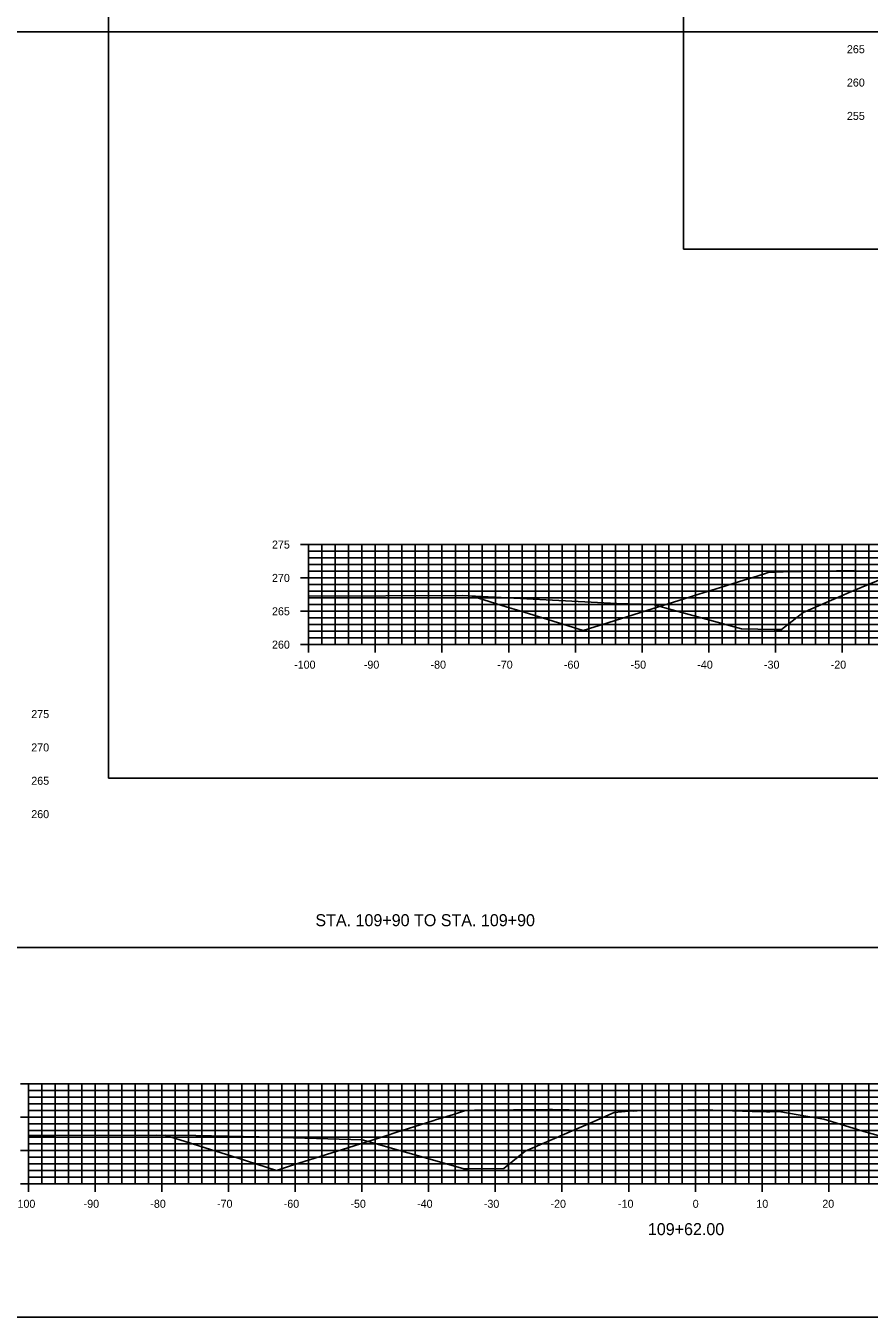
# Model space of a CAD drawing. Extents: x 1661012 to 1662122, y 670053 to 671852.
# Drawn here: x 1661264.3 to 1661390.7, y 671488.8 to 671682.4 of the extents above; entities that cross this region are included whole.
import ezdxf

# ---------------------------------------------------------------- set-up
doc = ezdxf.new("R2010")
doc.units = 0
for name, color, linetype in [('R_Concrete', 7, 'Continuous'), ('R_Concrete Hidden', 7, 'Continuous'), ('R_Erosion', 7, 'Continuous'), ('R_Exist Surface', 7, 'Continuous'), ('R_Proposed Road', 7, 'Continuous'), ('R_ROW Annot', 7, 'Continuous')]:
    doc.layers.add(name, color=color, linetype=linetype)

msp = doc.modelspace()

# ---------------------------------------------------------------- linework, layer by layer
at = {"layer": 'R_Concrete'}
for p, q in [((1661305.45, 671604.66), (1661307.85, 671604.66)), ((1661306.65, 671604.66), (1661506.65, 671604.66)), ((1661306.65, 671589.66), (1661306.65, 671604.66)), ((1661306.65, 671603.66), (1661506.65, 671603.66)), ((1661306.65, 671603.66), (1661307.25, 671603.66)), ((1661308.65, 671589.66), (1661308.65, 671604.66)), ((1661310.65, 671589.66), (1661310.65, 671604.66)), ((1661312.65, 671589.66), (1661312.65, 671604.66)), ((1661314.65, 671589.66), (1661314.65, 671604.66)), ((1661316.65, 671589.66), (1661316.65, 671604.66)), ((1661318.65, 671589.66), (1661318.65, 671604.66)), ((1661320.65, 671589.66), (1661320.65, 671604.66)), ((1661322.65, 671589.66), (1661322.65, 671604.66)), ((1661324.65, 671589.66), (1661324.65, 671604.66)), ((1661326.65, 671589.66), (1661326.65, 671604.66)), ((1661328.65, 671589.66), (1661328.65, 671604.66)), ((1661330.65, 671589.66), (1661330.65, 671604.66)), ((1661332.65, 671589.66), (1661332.65, 671604.66)), ((1661334.65, 671589.66), (1661334.65, 671604.66)), ((1661336.65, 671589.66), (1661336.65, 671604.66)), ((1661338.65, 671589.66), (1661338.65, 671604.66)), ((1661340.65, 671589.66), (1661340.65, 671604.66)), ((1661342.65, 671589.66), (1661342.65, 671604.66)), ((1661344.65, 671589.66), (1661344.65, 671604.66)), ((1661346.65, 671589.66), (1661346.65, 671604.66)), ((1661348.65, 671589.66), (1661348.65, 671604.66)), ((1661350.65, 671589.66), (1661350.65, 671604.66)), ((1661352.65, 671589.66), (1661352.65, 671604.66)), ((1661354.65, 671589.66), (1661354.65, 671604.66)), ((1661356.65, 671589.66), (1661356.65, 671604.66)), ((1661358.65, 671589.66), (1661358.65, 671604.66)), ((1661360.65, 671589.66), (1661360.65, 671604.66)), ((1661362.65, 671589.66), (1661362.65, 671604.66)), ((1661364.65, 671589.66), (1661364.65, 671604.66)), ((1661366.65, 671589.66), (1661366.65, 671604.66)), ((1661368.65, 671589.66), (1661368.65, 671604.66)), ((1661370.65, 671589.66), (1661370.65, 671604.66)), ((1661372.65, 671589.66), (1661372.65, 671604.66)), ((1661374.65, 671589.66), (1661374.65, 671604.66)), ((1661376.65, 671589.66), (1661376.65, 671604.66)), ((1661378.65, 671589.66), (1661378.65, 671604.66)), ((1661380.65, 671589.66), (1661380.65, 671604.66)), ((1661382.65, 671589.66), (1661382.65, 671604.66)), ((1661384.65, 671589.66), (1661384.65, 671604.66)), ((1661386.65, 671589.66), (1661386.65, 671604.66)), ((1661388.65, 671589.66), (1661388.65, 671604.66)), ((1661390.65, 671589.66), (1661390.65, 671604.66)), ((1661306.65, 671602.66), (1661506.65, 671602.66)), ((1661306.65, 671602.66), (1661307.25, 671602.66)), ((1661306.65, 671601.66), (1661506.65, 671601.66)), ((1661306.65, 671601.66), (1661307.25, 671601.66)), ((1661305.45, 671599.66), (1661307.85, 671599.66)), ((1661306.65, 671600.66), (1661506.65, 671600.66)), ((1661306.65, 671600.66), (1661307.25, 671600.66)), ((1661306.65, 671599.66), (1661506.65, 671599.66)), ((1661306.65, 671598.66), (1661506.65, 671598.66)), ((1661306.65, 671598.66), (1661307.25, 671598.66)), ((1661306.65, 671597.66), (1661506.65, 671597.66)), ((1661306.65, 671597.66), (1661307.25, 671597.66)), ((1661306.65, 671596.66), (1661506.65, 671596.66)), ((1661306.65, 671596.66), (1661307.25, 671596.66)), ((1661306.65, 671595.66), (1661506.65, 671595.66)), ((1661306.65, 671595.66), (1661307.25, 671595.66)), ((1661305.45, 671594.66), (1661307.85, 671594.66)), ((1661306.65, 671594.66), (1661506.65, 671594.66)), ((1661306.65, 671593.66), (1661506.65, 671593.66)), ((1661306.65, 671593.66), (1661307.25, 671593.66)), ((1661306.65, 671592.66), (1661506.65, 671592.66)), ((1661306.65, 671592.66), (1661307.25, 671592.66)), ((1661306.65, 671591.66), (1661506.65, 671591.66)), ((1661306.65, 671591.66), (1661307.25, 671591.66)), ((1661305.45, 671589.66), (1661307.85, 671589.66)), ((1661306.65, 671588.46), (1661306.65, 671590.86)), ((1661306.65, 671590.66), (1661506.65, 671590.66)), ((1661306.65, 671590.66), (1661307.25, 671590.66)), ((1661306.65, 671589.66), (1661506.65, 671589.66)), ((1661308.65, 671589.66), (1661308.65, 671590.26)), ((1661310.65, 671589.66), (1661310.65, 671590.26)), ((1661312.65, 671589.66), (1661312.65, 671590.26)), ((1661314.65, 671589.66), (1661314.65, 671590.26)), ((1661316.65, 671588.46), (1661316.65, 671590.86)), ((1661318.65, 671589.66), (1661318.65, 671590.26)), ((1661320.65, 671589.66), (1661320.65, 671590.26)), ((1661322.65, 671589.66), (1661322.65, 671590.26)), ((1661324.65, 671589.66), (1661324.65, 671590.26)), ((1661326.65, 671588.46), (1661326.65, 671590.86)), ((1661328.65, 671589.66), (1661328.65, 671590.26)), ((1661330.65, 671589.66), (1661330.65, 671590.26)), ((1661332.65, 671589.66), (1661332.65, 671590.26)), ((1661334.65, 671589.66), (1661334.65, 671590.26)), ((1661336.65, 671588.46), (1661336.65, 671590.86)), ((1661338.65, 671589.66), (1661338.65, 671590.26)), ((1661340.65, 671589.66), (1661340.65, 671590.26)), ((1661342.65, 671589.66), (1661342.65, 671590.26)), ((1661344.65, 671589.66), (1661344.65, 671590.26)), ((1661346.65, 671588.46), (1661346.65, 671590.86)), ((1661348.65, 671589.66), (1661348.65, 671590.26)), ((1661350.65, 671589.66), (1661350.65, 671590.26)), ((1661352.65, 671589.66), (1661352.65, 671590.26)), ((1661354.65, 671589.66), (1661354.65, 671590.26)), ((1661356.65, 671588.46), (1661356.65, 671590.86)), ((1661358.65, 671589.66), (1661358.65, 671590.26)), ((1661360.65, 671589.66), (1661360.65, 671590.26)), ((1661362.65, 671589.66), (1661362.65, 671590.26)), ((1661364.65, 671589.66), (1661364.65, 671590.26)), ((1661366.65, 671588.46), (1661366.65, 671590.86)), ((1661368.65, 671589.66), (1661368.65, 671590.26)), ((1661370.65, 671589.66), (1661370.65, 671590.26)), ((1661372.65, 671589.66), (1661372.65, 671590.26)), ((1661374.65, 671589.66), (1661374.65, 671590.26)), ((1661376.65, 671588.46), (1661376.65, 671590.86)), ((1661378.65, 671589.66), (1661378.65, 671590.26)), ((1661380.65, 671589.66), (1661380.65, 671590.26)), ((1661382.65, 671589.66), (1661382.65, 671590.26)), ((1661384.65, 671589.66), (1661384.65, 671590.26)), ((1661386.65, 671588.46), (1661386.65, 671590.86)), ((1661388.65, 671589.66), (1661388.65, 671590.26)), ((1661390.65, 671589.66), (1661390.65, 671590.26)), ((1661263.44, 671523.84), (1661265.84, 671523.84)), ((1661264.64, 671523.84), (1661464.64, 671523.84)), ((1661264.64, 671508.84), (1661264.64, 671523.84)), ((1661266.64, 671508.84), (1661266.64, 671523.84)), ((1661268.64, 671508.84), (1661268.64, 671523.84)), ((1661270.64, 671508.84), (1661270.64, 671523.84)), ((1661272.64, 671508.84), (1661272.64, 671523.84)), ((1661274.64, 671508.84), (1661274.64, 671523.84)), ((1661276.64, 671508.84), (1661276.64, 671523.84)), ((1661278.64, 671508.84), (1661278.64, 671523.84)), ((1661280.64, 671508.84), (1661280.64, 671523.84)), ((1661282.64, 671508.84), (1661282.64, 671523.84)), ((1661284.64, 671508.84), (1661284.64, 671523.84)), ((1661286.64, 671508.84), (1661286.64, 671523.84)), ((1661288.64, 671508.84), (1661288.64, 671523.84)), ((1661290.64, 671508.84), (1661290.64, 671523.84)), ((1661292.64, 671508.84), (1661292.64, 671523.84)), ((1661294.64, 671508.84), (1661294.64, 671523.84)), ((1661296.64, 671508.84), (1661296.64, 671523.84)), ((1661298.64, 671508.84), (1661298.64, 671523.84)), ((1661300.64, 671508.84), (1661300.64, 671523.84)), ((1661302.64, 671508.84), (1661302.64, 671523.84)), ((1661304.64, 671508.84), (1661304.64, 671523.84)), ((1661306.64, 671508.84), (1661306.64, 671523.84)), ((1661308.64, 671508.84), (1661308.64, 671523.84)), ((1661310.64, 671508.84), (1661310.64, 671523.84)), ((1661312.64, 671508.84), (1661312.64, 671523.84)), ((1661314.64, 671508.84), (1661314.64, 671523.84)), ((1661316.64, 671508.84), (1661316.64, 671523.84)), ((1661318.64, 671508.84), (1661318.64, 671523.84)), ((1661320.64, 671508.84), (1661320.64, 671523.84)), ((1661322.64, 671508.84), (1661322.64, 671523.84)), ((1661324.64, 671508.84), (1661324.64, 671523.84)), ((1661326.64, 671508.84), (1661326.64, 671523.84)), ((1661328.64, 671508.84), (1661328.64, 671523.84)), ((1661330.64, 671508.84), (1661330.64, 671523.84)), ((1661332.64, 671508.84), (1661332.64, 671523.84)), ((1661334.64, 671508.84), (1661334.64, 671523.84)), ((1661336.64, 671508.84), (1661336.64, 671523.84)), ((1661338.64, 671508.84), (1661338.64, 671523.84)), ((1661340.64, 671508.84), (1661340.64, 671523.84)), ((1661342.64, 671508.84), (1661342.64, 671523.84)), ((1661344.64, 671508.84), (1661344.64, 671523.84)), ((1661346.64, 671508.84), (1661346.64, 671523.84)), ((1661348.64, 671508.84), (1661348.64, 671523.84)), ((1661350.64, 671508.84), (1661350.64, 671523.84)), ((1661352.64, 671508.84), (1661352.64, 671523.84)), ((1661354.64, 671508.84), (1661354.64, 671523.84)), ((1661356.64, 671508.84), (1661356.64, 671523.84)), ((1661358.64, 671508.84), (1661358.64, 671523.84)), ((1661360.64, 671508.84), (1661360.64, 671523.84)), ((1661362.64, 671508.84), (1661362.64, 671523.84)), ((1661364.64, 671508.84), (1661364.64, 671523.84)), ((1661366.64, 671508.84), (1661366.64, 671523.84)), ((1661368.64, 671508.84), (1661368.64, 671523.84)), ((1661370.64, 671508.84), (1661370.64, 671523.84)), ((1661372.64, 671508.84), (1661372.64, 671523.84)), ((1661374.64, 671508.84), (1661374.64, 671523.84)), ((1661376.64, 671508.84), (1661376.64, 671523.84)), ((1661378.64, 671508.84), (1661378.64, 671523.84)), ((1661380.64, 671508.84), (1661380.64, 671523.84)), ((1661382.64, 671508.84), (1661382.64, 671523.84)), ((1661384.64, 671508.84), (1661384.64, 671523.84)), ((1661386.64, 671508.84), (1661386.64, 671523.84)), ((1661388.64, 671508.84), (1661388.64, 671523.84)), ((1661390.64, 671508.84), (1661390.64, 671523.84)), ((1661264.64, 671522.84), (1661464.64, 671522.84)), ((1661264.64, 671522.84), (1661265.24, 671522.84)), ((1661264.64, 671521.84), (1661464.64, 671521.84)), ((1661264.64, 671521.84), (1661265.24, 671521.84)), ((1661264.64, 671520.84), (1661464.64, 671520.84)), ((1661264.64, 671520.84), (1661265.24, 671520.84)), ((1661264.64, 671519.84), (1661464.64, 671519.84)), ((1661264.64, 671519.84), (1661265.24, 671519.84)), ((1661263.44, 671518.84), (1661265.84, 671518.84)), ((1661264.64, 671518.84), (1661464.64, 671518.84)), ((1661264.64, 671517.84), (1661464.64, 671517.84)), ((1661264.64, 671517.84), (1661265.24, 671517.84)), ((1661264.64, 671516.84), (1661464.64, 671516.84)), ((1661264.64, 671516.84), (1661265.24, 671516.84)), ((1661264.64, 671515.84), (1661464.64, 671515.84)), ((1661264.64, 671515.84), (1661265.24, 671515.84)), ((1661264.64, 671514.84), (1661464.64, 671514.84)), ((1661264.64, 671514.84), (1661265.24, 671514.84)), ((1661263.44, 671513.84), (1661265.84, 671513.84)), ((1661264.64, 671513.84), (1661464.64, 671513.84)), ((1661264.64, 671512.84), (1661464.64, 671512.84)), ((1661264.64, 671512.84), (1661265.24, 671512.84)), ((1661264.64, 671511.84), (1661464.64, 671511.84)), ((1661264.64, 671511.84), (1661265.24, 671511.84)), ((1661264.64, 671510.84), (1661464.64, 671510.84)), ((1661264.64, 671510.84), (1661265.24, 671510.84)), ((1661263.44, 671508.84), (1661265.84, 671508.84)), ((1661264.64, 671507.64), (1661264.64, 671510.04)), ((1661264.64, 671509.84), (1661464.64, 671509.84)), ((1661264.64, 671509.84), (1661265.24, 671509.84)), ((1661264.64, 671508.84), (1661464.64, 671508.84)), ((1661266.64, 671508.84), (1661266.64, 671509.44)), ((1661268.64, 671508.84), (1661268.64, 671509.44)), ((1661270.64, 671508.84), (1661270.64, 671509.44)), ((1661272.64, 671508.84), (1661272.64, 671509.44)), ((1661274.64, 671507.64), (1661274.64, 671510.04)), ((1661276.64, 671508.84), (1661276.64, 671509.44)), ((1661278.64, 671508.84), (1661278.64, 671509.44)), ((1661280.64, 671508.84), (1661280.64, 671509.44)), ((1661282.64, 671508.84), (1661282.64, 671509.44)), ((1661284.64, 671507.64), (1661284.64, 671510.04)), ((1661286.64, 671508.84), (1661286.64, 671509.44)), ((1661288.64, 671508.84), (1661288.64, 671509.44)), ((1661290.64, 671508.84), (1661290.64, 671509.44)), ((1661292.64, 671508.84), (1661292.64, 671509.44)), ((1661294.64, 671507.64), (1661294.64, 671510.04)), ((1661296.64, 671508.84), (1661296.64, 671509.44)), ((1661298.64, 671508.84), (1661298.64, 671509.44)), ((1661300.64, 671508.84), (1661300.64, 671509.44)), ((1661302.64, 671508.84), (1661302.64, 671509.44)), ((1661304.64, 671507.64), (1661304.64, 671510.04)), ((1661306.64, 671508.84), (1661306.64, 671509.44)), ((1661308.64, 671508.84), (1661308.64, 671509.44)), ((1661310.64, 671508.84), (1661310.64, 671509.44)), ((1661312.64, 671508.84), (1661312.64, 671509.44)), ((1661314.64, 671507.64), (1661314.64, 671510.04)), ((1661316.64, 671508.84), (1661316.64, 671509.44)), ((1661318.64, 671508.84), (1661318.64, 671509.44)), ((1661320.64, 671508.84), (1661320.64, 671509.44)), ((1661322.64, 671508.84), (1661322.64, 671509.44)), ((1661324.64, 671507.64), (1661324.64, 671510.04)), ((1661326.64, 671508.84), (1661326.64, 671509.44)), ((1661328.64, 671508.84), (1661328.64, 671509.44)), ((1661330.64, 671508.84), (1661330.64, 671509.44)), ((1661332.64, 671508.84), (1661332.64, 671509.44)), ((1661334.64, 671507.64), (1661334.64, 671510.04)), ((1661336.64, 671508.84), (1661336.64, 671509.44)), ((1661338.64, 671508.84), (1661338.64, 671509.44)), ((1661340.64, 671508.84), (1661340.64, 671509.44)), ((1661342.64, 671508.84), (1661342.64, 671509.44)), ((1661344.64, 671507.64), (1661344.64, 671510.04)), ((1661346.64, 671508.84), (1661346.64, 671509.44)), ((1661348.64, 671508.84), (1661348.64, 671509.44)), ((1661350.64, 671508.84), (1661350.64, 671509.44)), ((1661352.64, 671508.84), (1661352.64, 671509.44)), ((1661354.64, 671507.64), (1661354.64, 671510.04)), ((1661356.64, 671508.84), (1661356.64, 671509.44)), ((1661358.64, 671508.84), (1661358.64, 671509.44)), ((1661360.64, 671508.84), (1661360.64, 671509.44)), ((1661362.64, 671508.84), (1661362.64, 671509.44)), ((1661364.64, 671507.64), (1661364.64, 671510.04)), ((1661366.64, 671508.84), (1661366.64, 671509.44)), ((1661368.64, 671508.84), (1661368.64, 671509.44)), ((1661370.64, 671508.84), (1661370.64, 671509.44)), ((1661372.64, 671508.84), (1661372.64, 671509.44)), ((1661374.64, 671507.64), (1661374.64, 671510.04)), ((1661376.64, 671508.84), (1661376.64, 671509.44)), ((1661378.64, 671508.84), (1661378.64, 671509.44)), ((1661380.64, 671508.84), (1661380.64, 671509.44)), ((1661382.64, 671508.84), (1661382.64, 671509.44)), ((1661384.64, 671507.64), (1661384.64, 671510.04)), ((1661386.64, 671508.84), (1661386.64, 671509.44)), ((1661388.64, 671508.84), (1661388.64, 671509.44)), ((1661390.64, 671508.84), (1661390.64, 671509.44))]:
    msp.add_line(p, q, dxfattribs=at)
at = {"layer": 'R_Erosion'}
for points in [[(1661306.65, 671596.95), (1661306.68, 671596.95), (1661329.74, 671597.02), (1661352.86, 671595.85), (1661358.3, 671595.68), (1661360.07, 671595.17), (1661371.57, 671592.01), (1661376.43, 671591.91), (1661377.53, 671591.92), (1661380.29, 671594.08), (1661380.78, 671594.48), (1661387.68, 671597.46), (1661388.06, 671597.62), (1661393.22, 671599.79)], [(1661264.64, 671516.09), (1661268.55, 671516.09), (1661283.91, 671516.12), (1661289.75, 671516.06), (1661299.22, 671515.9), (1661314.66, 671515.42), (1661328.38, 671511.52), (1661329.91, 671511.09), (1661330.55, 671511.08), (1661335.94, 671511.14), (1661336.22, 671511.36), (1661339.13, 671513.74), (1661340.18, 671514.2), (1661346.5, 671516.94), (1661348.51, 671517.78), (1661352.47, 671519.54), (1661354.68, 671519.7), (1661355.92, 671519.77), (1661363.49, 671519.88), (1661365.83, 671519.9), (1661373.16, 671519.68), (1661375.32, 671519.62), (1661375.8, 671519.62), (1661377.17, 671519.68), (1661381.48, 671518.92), (1661383.9, 671518.54), (1661390.25, 671516.56), (1661401.96, 671513.34)]]:
    msp.add_lwpolyline(points, dxfattribs=at)
at = {"layer": 'R_Exist Surface'}
for p, q in [((1661306.65, 671589.66), (1661306.65, 671604.66)), ((1661306.65, 671589.66), (1661506.65, 671589.66)), ((1661264.64, 671508.84), (1661264.64, 671523.84)), ((1661264.64, 671508.84), (1661464.64, 671508.84))]:
    msp.add_line(p, q, dxfattribs=at)
at = {"layer": 'R_Proposed Road'}
for points in [[(1661362.85, 671648.92), (1661722.85, 671648.92), (1661722.85, 671841.62), (1661362.85, 671841.62)], [(1661276.65, 671569.66), (1661636.65, 671569.66), (1661636.65, 671762.36), (1661276.65, 671762.36)], [(1661032.67, 671544.25), (1661392.67, 671544.25), (1661392.67, 671736.95), (1661032.67, 671736.95)], [(1661234.64, 671488.84), (1661594.64, 671488.84), (1661594.64, 671681.54), (1661234.64, 671681.54)]]:
    msp.add_lwpolyline(points, close=True, dxfattribs=at)
at = {"layer": 'R_ROW Annot'}
for points in [[(1661331.12, 671596.95), (1661331.25, 671596.91), (1661331.3, 671596.89), (1661336.26, 671595.35), (1661338.32, 671594.72), (1661342.5, 671593.42), (1661347.82, 671591.78), (1661349.57, 671592.33), (1661350.71, 671592.69), (1661351.35, 671592.89), (1661351.5, 671592.94), (1661357.36, 671594.77), (1661363.75, 671596.78), (1661364.06, 671596.87), (1661365.15, 671597.21), (1661367.1, 671597.82), (1661368.42, 671598.24), (1661370.18, 671598.78), (1661371.9, 671599.32), (1661373.09, 671599.69), (1661375.16, 671600.34), (1661375.38, 671600.4), (1661375.71, 671600.51), (1661376.6, 671600.54), (1661377.63, 671600.57), (1661377.78, 671600.58), (1661377.82, 671600.58), (1661385.82, 671600.72), (1661386.35, 671600.73), (1661388.43, 671600.77), (1661388.44, 671600.77)], [(1661285.1, 671516.11), (1661288.93, 671514.91), (1661290.32, 671514.47), (1661295.93, 671512.71), (1661301.86, 671510.85), (1661303.77, 671511.46), (1661305.2, 671511.91), (1661311.74, 671513.99), (1661318.88, 671516.25), (1661319.13, 671516.33), (1661319.75, 671516.53), (1661322.6, 671517.43), (1661325.29, 671518.28), (1661325.82, 671518.45), (1661326.37, 671518.62), (1661328.35, 671519.24), (1661330.19, 671519.83), (1661330.53, 671519.83), (1661331.52, 671519.86), (1661332.17, 671519.88), (1661332.29, 671519.88), (1661337.37, 671519.92), (1661342.53, 671519.98), (1661342.54, 671519.98), (1661342.77, 671519.99), (1661343.2, 671519.98), (1661343.23, 671519.98), (1661353.28, 671519.78), (1661353.42, 671519.77), (1661354.11, 671519.76), (1661355.4, 671519.74)]]:
    msp.add_lwpolyline(points, dxfattribs=at)

# ---------------------------------------------------------------- texts
at = {"layer": 'R_Concrete Hidden'}
for s, height, p in [('265', 1.2, (1661387.36, 671678.32)), ('260', 1.2, (1661387.36, 671673.32)), ('255', 1.2, (1661387.36, 671668.32)), ('275', 1.2, (1661301.16, 671604.06)), ('270', 1.2, (1661301.16, 671599.06)), ('265', 1.2, (1661301.16, 671594.06)), ('260', 1.2, (1661301.16, 671589.06)), ('-100', 1.2, (1661304.48, 671586.06)), ('-90', 1.2, (1661314.93, 671586.06)), ('-80', 1.2, (1661324.93, 671586.06)), ('-70', 1.2, (1661334.93, 671586.06)), ('-60', 1.2, (1661344.93, 671586.06)), ('-50', 1.2, (1661354.93, 671586.06)), ('-40', 1.2, (1661364.93, 671586.06)), ('-30', 1.2, (1661374.93, 671586.06)), ('-20', 1.2, (1661384.93, 671586.06)), ('275', 1.2, (1661265.07, 671578.65)), ('270', 1.2, (1661265.07, 671573.65)), ('265', 1.2, (1661265.07, 671568.65)), ('260', 1.2, (1661265.07, 671563.65)), ('STA. 109+90 TO STA. 109+90', 1.8, (1661307.67, 671547.45)), ('-100', 1.2, (1661262.47, 671505.24)), ('-90', 1.2, (1661272.92, 671505.24)), ('-80', 1.2, (1661282.92, 671505.24)), ('-70', 1.2, (1661292.92, 671505.24)), ('-60', 1.2, (1661302.92, 671505.24)), ('-50', 1.2, (1661312.92, 671505.24)), ('-40', 1.2, (1661322.92, 671505.24)), ('-30', 1.2, (1661332.92, 671505.24)), ('-20', 1.2, (1661342.92, 671505.24)), ('-10', 1.2, (1661353.04, 671505.24)), ('0', 1.2, (1661364.24, 671505.24)), ('10', 1.2, (1661373.78, 671505.24)), ('20', 1.2, (1661383.67, 671505.24)), ('109+62.00', 1.8, (1661357.52, 671501.14))]:
    msp.add_text(s, height=height, dxfattribs=at).set_placement(p)
at = {"layer": 'R_Exist Surface'}
for p in [(1661306.65, 671589.66), (1661264.64, 671508.84)]:
    msp.add_text('-', height=0.0001, dxfattribs=at).set_placement(p)

doc.saveas('drawing.dxf')
